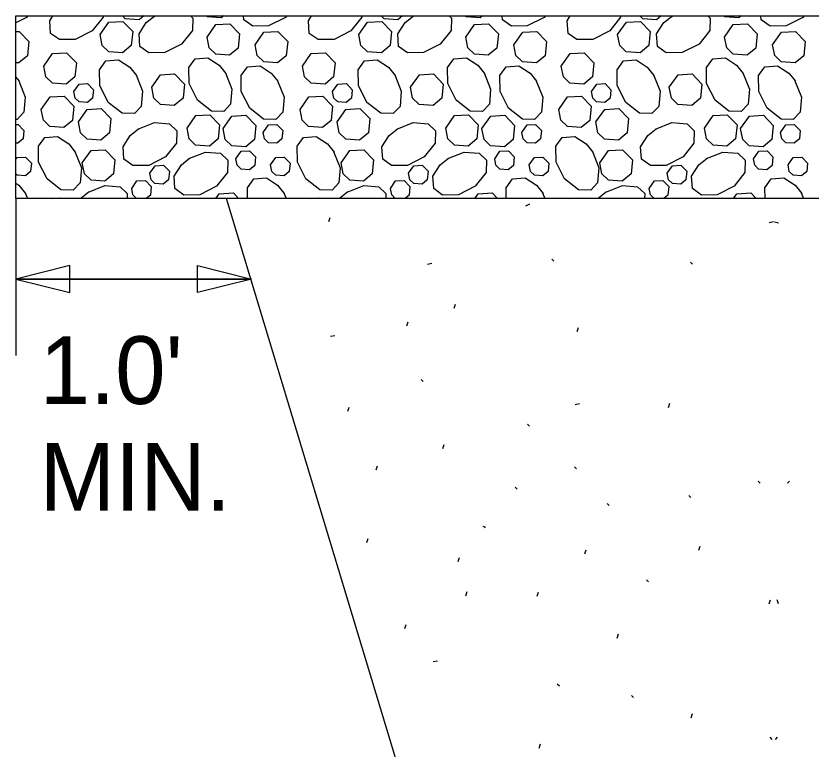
# Model space of a CAD drawing. Extents: x 9786.6 to 9853.1, y 9958.7 to 10011.2.
# Drawn here: x 9804.68 to 9816.93, y 9997.08 to 10008.38 of the extents above; entities that cross this region are included whole.
import ezdxf

# ---------------------------------------------------------------- set-up
doc = ezdxf.new("R2010")
doc.units = 0
for name, color, linetype in [('Default', 7, 'Continuous'), ('G-ANNO-TEXT', 7, 'Continuous'), ('G-DETL-LINE', 7, 'Continuous'), ('G-DETL-OTLN', 7, 'Continuous'), ('G-DETL-PATT', 7, 'Continuous')]:
    doc.layers.add(name, color=color, linetype=linetype)

# ---------------------------------------------------------------- blocks, each defined once
blk = doc.blocks.new('TERARR')
at = {"layer": 'Default'}
blk.add_lwpolyline([(-0.6667, 0.1667), (0, 0), (-0.6667, -0.1667)], close=True, dxfattribs=at)

msp = doc.modelspace()

# ---------------------------------------------------------------- linework, layer by layer
at = {"layer": 'Default'}
for points in [[(9806.805, 10008.375), (9806.826, 10008.384)], [(9810.793, 10008.375), (9810.815, 10008.384)], [(9814.781, 10008.375), (9814.803, 10008.384)], [(9804.677, 10007.438), (9804.728, 10007.375)], [(9804.819, 10005.655), (9804.854, 10005.569)], [(9805.235, 10005.569), (9805.367, 10005.576), (9805.374, 10005.569)], [(9809.224, 10005.569), (9809.355, 10005.576), (9809.362, 10005.569)], [(9813.212, 10005.569), (9813.343, 10005.576), (9813.35, 10005.569)]]:
    msp.add_lwpolyline(points, dxfattribs=at)
at = {"layer": 'G-ANNO-TEXT'}
for p, q in [((9804.677, 10005.569), (9804.677, 10003.15)), ((9808.309, 10004.326), (9804.677, 10004.326)), ((9804.677, 10004.326), (9808.309, 10004.326))]:
    msp.add_line(p, q, dxfattribs=at)
at = {"layer": 'G-DETL-LINE'}
msp.add_lwpolyline([(9804.677, 10008.384), (9828.045, 10008.384), (9828.045, 10005.569), (9804.677, 10005.569)], close=True, dxfattribs=at)
at = {"layer": 'G-DETL-OTLN'}
msp.add_lwpolyline([(9825.286, 10005.569), (9820.093, 9988.373), (9820.093, 9984.842), (9813.116, 9984.842), (9813.116, 9988.373), (9807.923, 10005.569)], dxfattribs=at)
at = {"layer": 'G-DETL-PATT'}
for p, q in [((9812.593, 10005.483), (9812.53, 10005.452)), ((9809.5, 10005.212), (9809.521, 10005.275)), ((9816.353, 10005.208), (9816.288, 10005.194)), ((9816.369, 10005.208), (9816.434, 10005.194)), ((9811.088, 10004.564), (9811.023, 10004.55)), ((9812.971, 10004.603), (9812.94, 10004.635)), ((9815.105, 10004.557), (9815.074, 10004.588)), ((9811.435, 10003.877), (9811.456, 10003.94)), ((9810.701, 10003.604), (9810.722, 10003.667)), ((9813.329, 10003.516), (9813.35, 10003.579)), ((9809.593, 10003.453), (9809.529, 10003.439)), ((9810.954, 10002.744), (9810.922, 10002.775)), ((9809.793, 10002.288), (9809.814, 10002.351)), ((9813.364, 10002.401), (9813.299, 10002.387)), ((9814.735, 10002.347), (9814.756, 10002.41)), ((9812.593, 10002.058), (9812.562, 10002.09)), ((9811.259, 10001.713), (9811.28, 10001.776)), ((9810.232, 10001.382), (9810.253, 10001.445)), ((9813.317, 10001.399), (9813.286, 10001.43)), ((9812.404, 10001.084), (9812.373, 10001.116)), ((9816.152, 10001.179), (9816.12, 10001.21)), ((9816.57, 10001.179), (9816.602, 10001.21)), ((9815.081, 10000.959), (9815.05, 10000.99)), ((9813.821, 10000.833), (9813.79, 10000.864)), ((9811.875, 10000.518), (9811.901, 10000.504)), ((9811.901, 10000.504), (9811.913, 10000.49)), ((9810.087, 10000.263), (9810.108, 10000.326)), ((9813.447, 10000.087), (9813.468, 10000.15)), ((9815.205, 10000.146), (9815.226, 10000.209)), ((9811.494, 9999.97), (9811.515, 10000.033)), ((9814.431, 9999.656), (9814.4, 9999.687)), ((9811.611, 9999.444), (9811.632, 9999.507)), ((9812.713, 9999.435), (9812.734, 9999.497)), ((9816.289, 9999.318), (9816.31, 9999.38)), ((9816.433, 9999.318), (9816.412, 9999.38)), ((9810.672, 9998.937), (9810.693, 9999)), ((9813.944, 9998.791), (9813.965, 9998.854)), ((9811.176, 9998.436), (9811.111, 9998.422)), ((9813.054, 9998.048), (9813.022, 9998.079)), ((9814.197, 9997.872), (9814.165, 9997.904)), ((9815.087, 9997.563), (9815.108, 9997.626)), ((9816.336, 9997.229), (9816.305, 9997.261)), ((9816.386, 9997.229), (9816.417, 9997.261)), ((9812.743, 9997.095), (9812.764, 9997.158))]:
    msp.add_line(p, q, dxfattribs=at)
for points in [[(9804.862, 10008.384), (9804.843, 10008.36), (9804.677, 10008.277)], [(9806.021, 10008.384), (9806.021, 10008.366), (9805.853, 10008.152), (9805.593, 10008.022), (9805.349, 10008.018), (9805.211, 10008.115), (9805.198, 10008.31), (9805.245, 10008.384)], [(9806.649, 10008.384), (9806.577, 10008.324), (9806.364, 10008.34), (9806.318, 10008.384)], [(9807.366, 10008.384), (9807.402, 10008.35), (9807.398, 10008.161), (9807.23, 10007.947), (9806.971, 10007.817), (9806.726, 10007.813), (9806.588, 10007.91), (9806.575, 10008.105), (9806.687, 10008.28), (9806.815, 10008.382)], [(9807.88, 10008.384), (9807.843, 10008.354), (9807.63, 10008.369), (9807.615, 10008.384)], [(9808.85, 10008.384), (9808.831, 10008.36), (9808.572, 10008.23), (9808.327, 10008.226), (9808.189, 10008.324), (9808.185, 10008.384)], [(9810.01, 10008.384), (9810.009, 10008.366), (9809.841, 10008.152), (9809.582, 10008.022), (9809.337, 10008.018), (9809.199, 10008.115), (9809.186, 10008.31), (9809.234, 10008.384)], [(9810.637, 10008.384), (9810.566, 10008.324), (9810.352, 10008.34), (9810.306, 10008.384)], [(9811.355, 10008.384), (9811.39, 10008.35), (9811.387, 10008.161), (9811.219, 10007.947), (9810.959, 10007.817), (9810.714, 10007.813), (9810.577, 10007.91), (9810.564, 10008.105), (9810.675, 10008.28), (9810.803, 10008.382)], [(9811.868, 10008.384), (9811.832, 10008.354), (9811.618, 10008.369), (9811.603, 10008.384)], [(9812.839, 10008.384), (9812.82, 10008.36), (9812.56, 10008.23), (9812.316, 10008.226), (9812.178, 10008.324), (9812.174, 10008.384)], [(9813.998, 10008.384), (9813.998, 10008.366), (9813.83, 10008.152), (9813.57, 10008.022), (9813.325, 10008.018), (9813.188, 10008.115), (9813.175, 10008.31), (9813.222, 10008.384)], [(9814.625, 10008.384), (9814.554, 10008.324), (9814.34, 10008.34), (9814.295, 10008.384)], [(9815.343, 10008.384), (9815.378, 10008.35), (9815.375, 10008.161), (9815.207, 10007.947), (9814.947, 10007.817), (9814.703, 10007.813), (9814.565, 10007.91), (9814.552, 10008.105), (9814.664, 10008.28), (9814.792, 10008.382)], [(9815.856, 10008.384), (9815.82, 10008.354), (9815.607, 10008.369), (9815.591, 10008.384)], [(9816.827, 10008.384), (9816.808, 10008.36), (9816.549, 10008.23), (9816.304, 10008.226), (9816.166, 10008.324), (9816.162, 10008.384)], [(9805.975, 10008.095), (9806.111, 10008.288), (9806.327, 10008.3), (9806.478, 10008.144), (9806.456, 10007.926), (9806.322, 10007.814), (9806.109, 10007.83), (9806.008, 10007.927), (9805.975, 10008.095)], [(9807.624, 10008.057), (9807.76, 10008.25), (9807.976, 10008.262), (9808.126, 10008.106), (9808.105, 10007.888), (9807.971, 10007.777), (9807.757, 10007.792), (9807.657, 10007.889), (9807.624, 10008.057)], [(9809.964, 10008.095), (9810.099, 10008.288), (9810.316, 10008.3), (9810.466, 10008.144), (9810.444, 10007.926), (9810.311, 10007.814), (9810.097, 10007.83), (9809.996, 10007.927), (9809.964, 10008.095)], [(9811.612, 10008.057), (9811.748, 10008.25), (9811.964, 10008.262), (9812.115, 10008.106), (9812.093, 10007.888), (9811.959, 10007.777), (9811.746, 10007.792), (9811.645, 10007.889), (9811.613, 10008.057)], [(9813.952, 10008.095), (9814.088, 10008.288), (9814.304, 10008.3), (9814.454, 10008.144), (9814.433, 10007.926), (9814.299, 10007.814), (9814.085, 10007.83), (9813.985, 10007.927), (9813.952, 10008.095)], [(9815.601, 10008.057), (9815.736, 10008.25), (9815.953, 10008.262), (9816.103, 10008.106), (9816.081, 10007.888), (9815.948, 10007.777), (9815.734, 10007.792), (9815.634, 10007.889), (9815.601, 10008.057)], [(9804.677, 10008.141), (9804.728, 10008.144), (9804.879, 10007.988), (9804.857, 10007.77), (9804.723, 10007.659), (9804.677, 10007.662)], [(9808.365, 10007.939), (9808.5, 10008.132), (9808.717, 10008.144), (9808.867, 10007.988), (9808.845, 10007.77), (9808.712, 10007.659), (9808.498, 10007.674), (9808.398, 10007.771), (9808.365, 10007.939)], [(9812.353, 10007.939), (9812.489, 10008.132), (9812.705, 10008.144), (9812.856, 10007.988), (9812.834, 10007.77), (9812.7, 10007.659), (9812.487, 10007.674), (9812.386, 10007.771), (9812.353, 10007.939)], [(9816.342, 10007.939), (9816.477, 10008.132), (9816.694, 10008.144), (9816.844, 10007.988), (9816.822, 10007.77), (9816.688, 10007.659), (9816.475, 10007.674), (9816.374, 10007.771), (9816.342, 10007.939)], [(9805.106, 10007.611), (9805.242, 10007.804), (9805.458, 10007.816), (9805.609, 10007.66), (9805.587, 10007.442), (9805.453, 10007.331), (9805.24, 10007.346), (9805.139, 10007.444), (9805.107, 10007.611)], [(9807.906, 10007.508), (9808.007, 10007.254), (9807.986, 10007.022), (9807.881, 10006.911), (9807.692, 10006.914), (9807.478, 10007.082), (9807.348, 10007.342), (9807.344, 10007.587), (9807.441, 10007.724), (9807.636, 10007.737), (9807.811, 10007.626), (9807.913, 10007.498)], [(9809.095, 10007.611), (9809.23, 10007.804), (9809.447, 10007.816), (9809.597, 10007.66), (9809.575, 10007.442), (9809.442, 10007.331), (9809.228, 10007.346), (9809.128, 10007.444), (9809.095, 10007.611)], [(9811.894, 10007.508), (9811.995, 10007.254), (9811.975, 10007.022), (9811.87, 10006.911), (9811.681, 10006.914), (9811.466, 10007.082), (9811.336, 10007.342), (9811.332, 10007.587), (9811.43, 10007.724), (9811.625, 10007.737), (9811.799, 10007.626), (9811.901, 10007.498)], [(9813.083, 10007.611), (9813.219, 10007.804), (9813.435, 10007.816), (9813.585, 10007.66), (9813.564, 10007.442), (9813.43, 10007.331), (9813.216, 10007.346), (9813.116, 10007.444), (9813.083, 10007.611)], [(9815.883, 10007.508), (9815.983, 10007.254), (9815.963, 10007.022), (9815.858, 10006.911), (9815.669, 10006.914), (9815.454, 10007.082), (9815.324, 10007.342), (9815.32, 10007.587), (9815.418, 10007.724), (9815.613, 10007.737), (9815.787, 10007.626), (9815.889, 10007.498)], [(9806.529, 10007.475), (9806.629, 10007.222), (9806.609, 10006.989), (9806.504, 10006.878), (9806.315, 10006.882), (9806.1, 10007.05), (9805.971, 10007.309), (9805.966, 10007.554), (9806.064, 10007.692), (9806.259, 10007.705), (9806.433, 10007.593), (9806.535, 10007.465)], [(9808.709, 10007.385), (9808.81, 10007.132), (9808.79, 10006.899), (9808.685, 10006.788), (9808.496, 10006.791), (9808.281, 10006.959), (9808.151, 10007.219), (9808.147, 10007.464), (9808.245, 10007.601), (9808.44, 10007.614), (9808.614, 10007.503), (9808.716, 10007.375)], [(9810.517, 10007.475), (9810.618, 10007.222), (9810.598, 10006.989), (9810.492, 10006.878), (9810.303, 10006.882), (9810.089, 10007.05), (9809.959, 10007.309), (9809.955, 10007.554), (9810.053, 10007.692), (9810.247, 10007.705), (9810.422, 10007.593), (9810.524, 10007.465)], [(9812.698, 10007.385), (9812.798, 10007.132), (9812.778, 10006.899), (9812.673, 10006.788), (9812.484, 10006.791), (9812.269, 10006.959), (9812.14, 10007.219), (9812.135, 10007.464), (9812.233, 10007.601), (9812.428, 10007.614), (9812.602, 10007.503), (9812.704, 10007.375)], [(9814.506, 10007.475), (9814.606, 10007.222), (9814.586, 10006.989), (9814.481, 10006.878), (9814.292, 10006.882), (9814.077, 10007.05), (9813.947, 10007.309), (9813.943, 10007.554), (9814.041, 10007.692), (9814.236, 10007.705), (9814.41, 10007.593), (9814.512, 10007.465)], [(9816.686, 10007.385), (9816.787, 10007.132), (9816.767, 10006.899), (9816.661, 10006.788), (9816.472, 10006.791), (9816.258, 10006.959), (9816.128, 10007.219), (9816.124, 10007.464), (9816.221, 10007.601), (9816.416, 10007.614), (9816.591, 10007.503), (9816.693, 10007.375)], [(9806.772, 10007.283), (9806.908, 10007.476), (9807.124, 10007.488), (9807.275, 10007.333), (9807.253, 10007.114), (9807.119, 10007.003), (9806.906, 10007.018), (9806.805, 10007.116), (9806.772, 10007.283)], [(9810.761, 10007.283), (9810.896, 10007.476), (9811.113, 10007.488), (9811.263, 10007.333), (9811.241, 10007.114), (9811.108, 10007.003), (9810.894, 10007.018), (9810.793, 10007.116), (9810.761, 10007.283)], [(9814.749, 10007.283), (9814.885, 10007.476), (9815.101, 10007.488), (9815.251, 10007.333), (9815.23, 10007.114), (9815.096, 10007.003), (9814.882, 10007.018), (9814.782, 10007.116), (9814.749, 10007.283)], [(9804.721, 10007.385), (9804.822, 10007.132), (9804.802, 10006.899), (9804.696, 10006.788), (9804.677, 10006.788)], [(9805.572, 10007.216), (9805.653, 10007.332), (9805.783, 10007.339), (9805.873, 10007.246), (9805.86, 10007.115), (9805.78, 10007.048), (9805.652, 10007.057), (9805.592, 10007.116), (9805.572, 10007.216)], [(9809.56, 10007.216), (9809.642, 10007.332), (9809.771, 10007.339), (9809.862, 10007.246), (9809.849, 10007.115), (9809.768, 10007.048), (9809.64, 10007.057), (9809.58, 10007.116), (9809.56, 10007.216)], [(9813.549, 10007.216), (9813.63, 10007.332), (9813.76, 10007.339), (9813.85, 10007.246), (9813.837, 10007.115), (9813.757, 10007.048), (9813.629, 10007.057), (9813.568, 10007.116), (9813.549, 10007.216)], [(9805.068, 10006.942), (9805.204, 10007.135), (9805.42, 10007.147), (9805.571, 10006.991), (9805.549, 10006.773), (9805.415, 10006.661), (9805.202, 10006.677), (9805.101, 10006.774), (9805.069, 10006.942)], [(9809.057, 10006.942), (9809.192, 10007.135), (9809.409, 10007.147), (9809.559, 10006.991), (9809.537, 10006.773), (9809.404, 10006.661), (9809.19, 10006.677), (9809.09, 10006.774), (9809.057, 10006.942)], [(9813.045, 10006.942), (9813.181, 10007.135), (9813.397, 10007.147), (9813.547, 10006.991), (9813.526, 10006.773), (9813.392, 10006.661), (9813.178, 10006.677), (9813.078, 10006.774), (9813.045, 10006.942)], [(9805.641, 10006.75), (9805.777, 10006.943), (9805.993, 10006.956), (9806.143, 10006.8), (9806.122, 10006.581), (9805.988, 10006.47), (9805.774, 10006.485), (9805.674, 10006.583), (9805.641, 10006.75)], [(9807.315, 10006.655), (9807.45, 10006.848), (9807.667, 10006.86), (9807.817, 10006.704), (9807.795, 10006.486), (9807.661, 10006.374), (9807.448, 10006.39), (9807.347, 10006.487), (9807.315, 10006.655)], [(9809.629, 10006.75), (9809.765, 10006.943), (9809.981, 10006.956), (9810.132, 10006.8), (9810.11, 10006.581), (9809.976, 10006.47), (9809.763, 10006.485), (9809.662, 10006.583), (9809.63, 10006.75)], [(9811.303, 10006.655), (9811.438, 10006.848), (9811.655, 10006.86), (9811.805, 10006.704), (9811.783, 10006.486), (9811.65, 10006.374), (9811.436, 10006.39), (9811.336, 10006.487), (9811.303, 10006.655)], [(9813.618, 10006.75), (9813.753, 10006.943), (9813.97, 10006.956), (9814.12, 10006.8), (9814.098, 10006.581), (9813.965, 10006.47), (9813.751, 10006.485), (9813.65, 10006.583), (9813.618, 10006.75)], [(9815.291, 10006.655), (9815.427, 10006.848), (9815.643, 10006.86), (9815.794, 10006.704), (9815.772, 10006.486), (9815.638, 10006.374), (9815.425, 10006.39), (9815.324, 10006.487), (9815.291, 10006.655)], [(9806.559, 10006.637), (9806.812, 10006.738), (9807.045, 10006.718), (9807.156, 10006.612), (9807.152, 10006.424), (9806.984, 10006.209), (9806.725, 10006.079), (9806.48, 10006.075), (9806.342, 10006.173), (9806.329, 10006.367), (9806.441, 10006.542), (9806.569, 10006.644)], [(9807.872, 10006.647), (9808.008, 10006.84), (9808.224, 10006.852), (9808.374, 10006.696), (9808.353, 10006.477), (9808.219, 10006.366), (9808.005, 10006.382), (9807.905, 10006.479), (9807.872, 10006.647)], [(9810.547, 10006.637), (9810.801, 10006.738), (9811.033, 10006.718), (9811.144, 10006.612), (9811.141, 10006.424), (9810.973, 10006.209), (9810.713, 10006.079), (9810.468, 10006.075), (9810.331, 10006.173), (9810.318, 10006.367), (9810.429, 10006.542), (9810.557, 10006.644)], [(9811.86, 10006.647), (9811.996, 10006.84), (9812.212, 10006.852), (9812.363, 10006.696), (9812.341, 10006.477), (9812.207, 10006.366), (9811.994, 10006.382), (9811.893, 10006.479), (9811.861, 10006.647)], [(9814.535, 10006.637), (9814.789, 10006.738), (9815.022, 10006.718), (9815.132, 10006.612), (9815.129, 10006.424), (9814.961, 10006.209), (9814.701, 10006.079), (9814.457, 10006.075), (9814.319, 10006.173), (9814.306, 10006.367), (9814.418, 10006.542), (9814.546, 10006.644)], [(9815.849, 10006.647), (9815.984, 10006.84), (9816.201, 10006.852), (9816.351, 10006.696), (9816.329, 10006.477), (9816.196, 10006.366), (9815.982, 10006.382), (9815.881, 10006.479), (9815.849, 10006.647)], [(9804.677, 10006.708), (9804.711, 10006.71), (9804.802, 10006.617), (9804.789, 10006.486), (9804.708, 10006.419), (9804.677, 10006.421)], [(9808.489, 10006.587), (9808.57, 10006.703), (9808.7, 10006.71), (9808.79, 10006.617), (9808.777, 10006.486), (9808.697, 10006.419), (9808.569, 10006.428), (9808.508, 10006.487), (9808.489, 10006.587)], [(9812.477, 10006.587), (9812.558, 10006.703), (9812.688, 10006.71), (9812.778, 10006.617), (9812.765, 10006.486), (9812.685, 10006.419), (9812.557, 10006.428), (9812.497, 10006.487), (9812.477, 10006.587)], [(9816.465, 10006.587), (9816.547, 10006.703), (9816.676, 10006.71), (9816.767, 10006.617), (9816.754, 10006.486), (9816.673, 10006.419), (9816.545, 10006.428), (9816.485, 10006.487), (9816.465, 10006.587)], [(9805.586, 10006.295), (9805.687, 10006.041), (9805.667, 10005.808), (9805.561, 10005.698), (9805.372, 10005.701), (9805.158, 10005.869), (9805.028, 10006.129), (9805.024, 10006.373), (9805.121, 10006.511), (9805.316, 10006.524), (9805.491, 10006.412), (9805.593, 10006.284)], [(9809.575, 10006.295), (9809.675, 10006.041), (9809.655, 10005.808), (9809.55, 10005.698), (9809.361, 10005.701), (9809.146, 10005.869), (9809.016, 10006.129), (9809.012, 10006.373), (9809.11, 10006.511), (9809.305, 10006.524), (9809.479, 10006.412), (9809.581, 10006.284)], [(9813.563, 10006.295), (9813.663, 10006.041), (9813.643, 10005.808), (9813.538, 10005.698), (9813.349, 10005.701), (9813.134, 10005.869), (9813.005, 10006.129), (9813, 10006.373), (9813.098, 10006.511), (9813.293, 10006.524), (9813.467, 10006.412), (9813.569, 10006.284)], [(9805.701, 10006.116), (9805.837, 10006.309), (9806.053, 10006.321), (9806.204, 10006.165), (9806.182, 10005.947), (9806.048, 10005.836), (9805.835, 10005.851), (9805.734, 10005.949), (9805.701, 10006.116)], [(9807.345, 10006.184), (9807.599, 10006.285), (9807.832, 10006.265), (9807.942, 10006.16), (9807.939, 10005.971), (9807.771, 10005.756), (9807.511, 10005.626), (9807.267, 10005.622), (9807.129, 10005.72), (9807.116, 10005.915), (9807.228, 10006.089), (9807.355, 10006.191)], [(9808.069, 10006.181), (9808.151, 10006.296), (9808.28, 10006.304), (9808.371, 10006.21), (9808.358, 10006.079), (9808.277, 10006.012), (9808.149, 10006.022), (9808.089, 10006.08), (9808.069, 10006.181)], [(9809.69, 10006.116), (9809.825, 10006.309), (9810.042, 10006.321), (9810.192, 10006.165), (9810.17, 10005.947), (9810.037, 10005.836), (9809.823, 10005.851), (9809.722, 10005.949), (9809.69, 10006.116)], [(9811.334, 10006.184), (9811.587, 10006.285), (9811.82, 10006.265), (9811.931, 10006.16), (9811.927, 10005.971), (9811.759, 10005.756), (9811.5, 10005.626), (9811.255, 10005.622), (9811.117, 10005.72), (9811.104, 10005.915), (9811.216, 10006.089), (9811.344, 10006.191)], [(9812.058, 10006.181), (9812.139, 10006.296), (9812.269, 10006.304), (9812.359, 10006.21), (9812.346, 10006.079), (9812.266, 10006.012), (9812.138, 10006.022), (9812.077, 10006.08), (9812.058, 10006.181)], [(9813.678, 10006.116), (9813.814, 10006.309), (9814.03, 10006.321), (9814.18, 10006.165), (9814.159, 10005.947), (9814.025, 10005.836), (9813.811, 10005.851), (9813.711, 10005.949), (9813.678, 10006.116)], [(9815.322, 10006.184), (9815.575, 10006.285), (9815.808, 10006.265), (9815.919, 10006.16), (9815.915, 10005.971), (9815.747, 10005.756), (9815.488, 10005.626), (9815.243, 10005.622), (9815.106, 10005.72), (9815.092, 10005.915), (9815.204, 10006.089), (9815.332, 10006.191)], [(9816.046, 10006.181), (9816.127, 10006.296), (9816.257, 10006.304), (9816.347, 10006.21), (9816.334, 10006.079), (9816.254, 10006.012), (9816.126, 10006.022), (9816.066, 10006.08), (9816.046, 10006.181)], [(9804.677, 10006.174), (9804.696, 10006.201), (9804.826, 10006.208), (9804.916, 10006.115), (9804.903, 10005.984), (9804.823, 10005.917), (9804.695, 10005.926), (9804.677, 10005.943)], [(9808.603, 10006.085), (9808.684, 10006.201), (9808.814, 10006.208), (9808.904, 10006.115), (9808.891, 10005.984), (9808.811, 10005.917), (9808.683, 10005.926), (9808.623, 10005.985), (9808.603, 10006.085)], [(9812.591, 10006.085), (9812.673, 10006.201), (9812.802, 10006.208), (9812.893, 10006.115), (9812.88, 10005.984), (9812.799, 10005.917), (9812.671, 10005.926), (9812.611, 10005.985), (9812.591, 10006.085)], [(9816.58, 10006.085), (9816.661, 10006.201), (9816.791, 10006.208), (9816.881, 10006.115), (9816.868, 10005.984), (9816.788, 10005.917), (9816.66, 10005.926), (9816.599, 10005.985), (9816.58, 10006.085)], [(9806.741, 10005.958), (9806.823, 10006.074), (9806.952, 10006.081), (9807.043, 10005.988), (9807.03, 10005.857), (9806.949, 10005.79), (9806.821, 10005.799), (9806.761, 10005.858), (9806.741, 10005.958)], [(9810.73, 10005.958), (9810.811, 10006.074), (9810.941, 10006.081), (9811.031, 10005.988), (9811.018, 10005.857), (9810.938, 10005.79), (9810.809, 10005.799), (9810.749, 10005.858), (9810.73, 10005.958)], [(9814.718, 10005.958), (9814.799, 10006.074), (9814.929, 10006.081), (9815.019, 10005.988), (9815.006, 10005.857), (9814.926, 10005.79), (9814.798, 10005.799), (9814.738, 10005.858), (9814.718, 10005.958)], [(9808.248, 10005.569), (9808.245, 10005.734), (9808.343, 10005.872), (9808.538, 10005.885), (9808.712, 10005.773), (9808.814, 10005.645)], [(9812.236, 10005.569), (9812.234, 10005.734), (9812.331, 10005.872), (9812.526, 10005.885), (9812.701, 10005.773), (9812.803, 10005.645)], [(9816.225, 10005.569), (9816.222, 10005.734), (9816.32, 10005.872), (9816.515, 10005.885), (9816.689, 10005.773), (9816.791, 10005.645)], [(9804.677, 10005.803), (9804.724, 10005.773), (9804.826, 10005.645)], [(9805.796, 10005.668), (9806.05, 10005.769), (9806.282, 10005.748), (9806.393, 10005.643), (9806.392, 10005.569)], [(9806.462, 10005.723), (9806.543, 10005.839), (9806.673, 10005.846), (9806.763, 10005.753), (9806.75, 10005.621), (9806.686, 10005.569)], [(9809.784, 10005.668), (9810.038, 10005.769), (9810.271, 10005.748), (9810.381, 10005.643), (9810.38, 10005.569)], [(9810.45, 10005.723), (9810.531, 10005.839), (9810.661, 10005.846), (9810.751, 10005.753), (9810.738, 10005.621), (9810.675, 10005.569)], [(9813.773, 10005.668), (9814.026, 10005.769), (9814.259, 10005.748), (9814.37, 10005.643), (9814.368, 10005.569)], [(9814.438, 10005.723), (9814.52, 10005.839), (9814.649, 10005.846), (9814.74, 10005.753), (9814.727, 10005.621), (9814.663, 10005.569)], [(9805.676, 10005.569), (9805.678, 10005.573), (9805.806, 10005.675)], [(9806.537, 10005.569), (9806.481, 10005.623), (9806.462, 10005.723)], [(9807.761, 10005.569), (9807.813, 10005.642), (9808.029, 10005.654), (9808.111, 10005.569)], [(9808.808, 10005.655), (9808.842, 10005.569)], [(9809.664, 10005.569), (9809.667, 10005.573), (9809.795, 10005.675)], [(9810.525, 10005.569), (9810.47, 10005.623), (9810.45, 10005.723)], [(9811.75, 10005.569), (9811.801, 10005.642), (9812.017, 10005.654), (9812.1, 10005.569)], [(9812.796, 10005.655), (9812.83, 10005.569)], [(9813.652, 10005.569), (9813.655, 10005.573), (9813.783, 10005.675)], [(9814.514, 10005.569), (9814.458, 10005.623), (9814.438, 10005.723)], [(9815.738, 10005.569), (9815.789, 10005.642), (9816.006, 10005.654), (9816.088, 10005.569)], [(9816.784, 10005.655), (9816.819, 10005.569)]]:
    msp.add_lwpolyline(points, dxfattribs=at)

# ---------------------------------------------------------------- block references
at = {"layer": 'G-ANNO-TEXT', "xscale": 1.25, "yscale": -1.25, "rotation": 180}
msp.add_blockref('TERARR', (9804.677, 10004.326), dxfattribs=at)
at = {"layer": 'G-ANNO-TEXT', "xscale": 1.25, "yscale": 1.25}
msp.add_blockref('TERARR', (9808.309, 10004.326), dxfattribs=at)

# ---------------------------------------------------------------- texts
at = {"layer": 'G-ANNO-TEXT'}
for s, p in [("1.0' ", (9805.044, 10002.4)), ('MIN.', (9805.044, 10000.756))]:
    msp.add_text(s, height=1.044, dxfattribs=at).set_placement(p)

doc.saveas('drawing.dxf')
